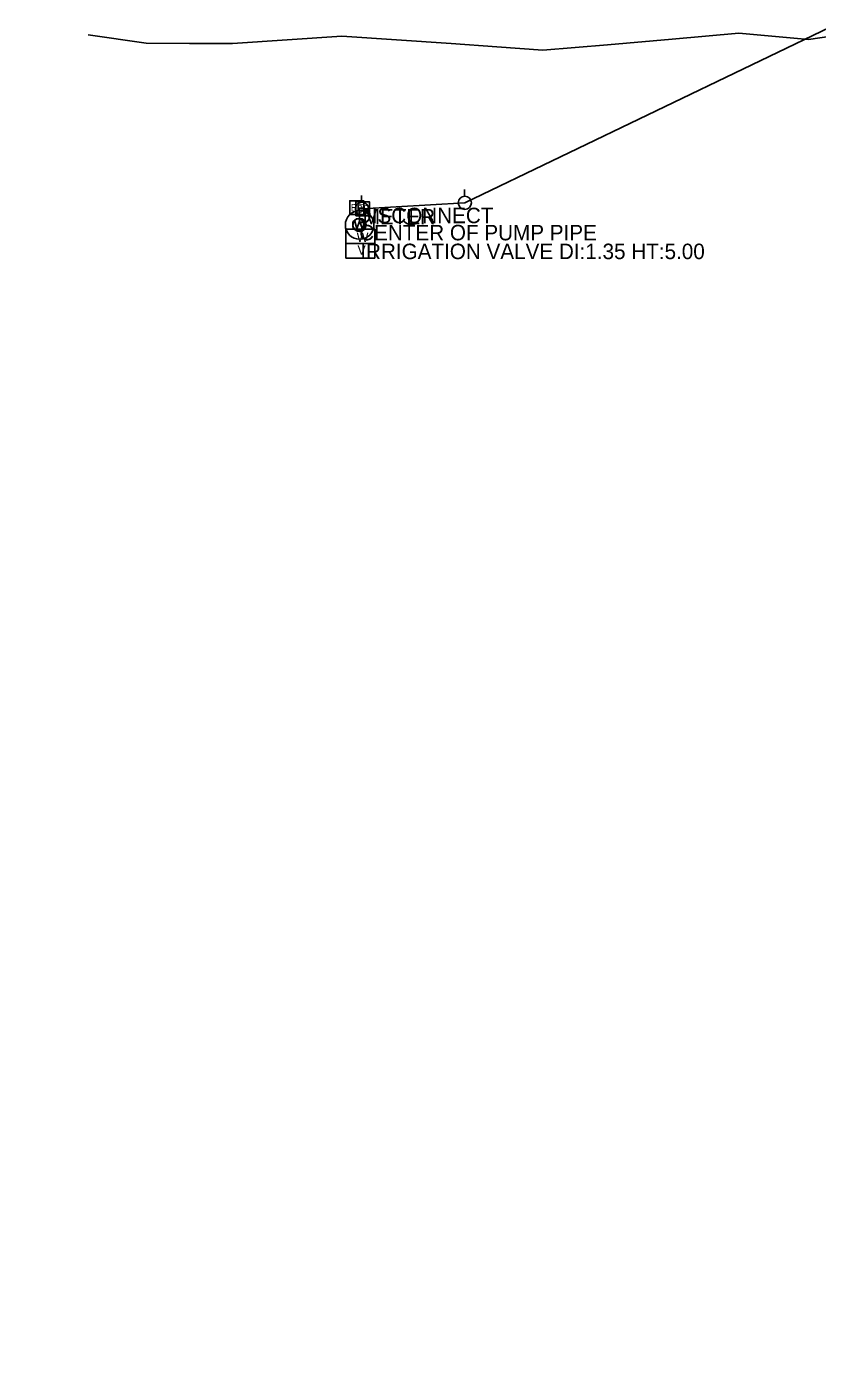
# Model space of a CAD drawing. Extents: x 1674300 to 1677920, y 225056 to 231852.
# Drawn here: x 1676889.4 to 1677145.4, y 228719.7 to 229147 of the extents above; entities that cross this region are included whole.
import ezdxf

# ---------------------------------------------------------------- set-up
doc = ezdxf.new("R2010")
doc.units = 0
for name, color, linetype in [('R_Horz Alg', 7, 'Continuous'), ('S_EDGE_CONCRETE', 7, 'Continuous'), ('S_ELECTRIC_UTILITIES', 7, 'Continuous'), ('S_ELECTRIC_UTILITIES_ANNOT', 7, 'Continuous'), ('S_EXIST_ROW', 7, 'Continuous'), ('S_STREAM', 7, 'Continuous'), ('S_UTILITY_POLE', 7, 'Continuous'), ('S_UTL_PT_SYM', 7, 'Continuous'), ('S_WATER_UTILITIES', 7, 'Continuous'), ('S_WATER_UTILITIES_ANNOT', 7, 'Continuous'), ('S_WATER_WELL_ANNOT', 7, 'Continuous')]:
    doc.layers.add(name, color=color, linetype=linetype)

msp = doc.modelspace()

# ---------------------------------------------------------------- linework, layer by layer
at = {"layer": 'R_Horz Alg'}
msp.add_arc((1675928.16, 228988.54), 1449, 296.0624, 0.80558, dxfattribs=at)
at = {"layer": 'S_EDGE_CONCRETE'}
msp.add_lwpolyline([(1676995.02, 229083.8), (1676994.98, 229082.04), (1676996.14, 229081.03), (1676997.58, 229080.98), (1676998.8, 229082.15), (1676998.7, 229083.76), (1676997.57, 229084.6), (1676996.22, 229084.77)], close=True, dxfattribs=at)
at = {"layer": 'S_ELECTRIC_UTILITIES'}
for p, q in [((1677278.13, 229208.63), (1677031.23, 229090)), ((1677031.23, 229090), (1676997.94, 229088.05))]:
    msp.add_line(p, q, dxfattribs=at)
for points in [[(1676994, 229086.15), (1676994, 229090.65), (1676998.5, 229090.65), (1676998.5, 229086.15)], [(1676995.91, 229085.75), (1676995.91, 229090.25), (1677000.41, 229090.25), (1677000.41, 229085.75)]]:
    msp.add_lwpolyline(points, close=True, dxfattribs=at)
at = {"layer": 'S_EXIST_ROW'}
msp.add_arc((1675926.71, 228989.39), 1410.53, 295.94359, 0.85682, dxfattribs=at)
at = {"layer": 'S_STREAM'}
msp.add_lwpolyline([(1677183.04, 229148.43), (1677170.36, 229146.92), (1677156.37, 229144.85), (1677142.38, 229142.77), (1677119.88, 229144.84), (1677098.3, 229142.91), (1677077.37, 229141.12), (1677056.44, 229139.33), (1677041.62, 229140.43), (1677026.8, 229141.54), (1677009.09, 229142.72), (1676991.39, 229143.9), (1676973.72, 229142.72), (1676956.05, 229141.55), (1676942.08, 229141.57), (1676928.12, 229141.58), (1676909.38, 229144.28)], dxfattribs=at)
at = {"layer": 'S_UTILITY_POLE'}
for p, q in [((1677031.11, 229092.14), (1677031.11, 229094.25)), ((1676997.81, 229090.19), (1676997.81, 229092.3)), ((1677013.87, 229087.68), (1677013.87, 229082.95))]:
    msp.add_line(p, q, dxfattribs=at)
for centre in [(1676997.94, 229088.05), (1677031.23, 229090)]:
    msp.add_circle(centre, 2.13, dxfattribs=at)
msp.add_arc((1677013.93, 229086.37), 3.41, 226.3972, 313.6028, dxfattribs=at)
at = {"layer": 'S_UTL_PT_SYM'}
for points in [[(1677031.23, 229090), (1677031.23, 229090.05), (1677031.23, 229090), (1677031.18, 229090), (1677031.23, 229090), (1677031.23, 229089.95), (1677031.23, 229090), (1677031.28, 229090)], [(1676997.94, 229088.05), (1676997.94, 229088.1), (1676997.94, 229088.05), (1676997.89, 229088.05), (1676997.94, 229088.05), (1676997.94, 229088), (1676997.94, 229088.05), (1676997.99, 229088.05)]]:
    msp.add_lwpolyline(points, dxfattribs=at)
at = {"layer": 'S_WATER_UTILITIES'}
for p, q in [((1676992.68, 229081.46), (1677002.1, 229081.46)), ((1676992.68, 229072.04), (1676992.68, 229081.46)), ((1676995.63, 229084.08), (1676996.29, 229081.6)), ((1676996.29, 229081.6), (1676997.1, 229084.08)), ((1676997.1, 229084.08), (1676998.15, 229081.6)), ((1676998.15, 229081.6), (1676998.73, 229084.12)), ((1677002.1, 229081.46), (1677002.1, 229072.04)), ((1676992.68, 229076.77), (1677002.1, 229076.77)), ((1677002.1, 229072.04), (1676992.68, 229072.04))]:
    msp.add_line(p, q, dxfattribs=at)
for centre, radius in [((1676997.19, 229082.82), 4.63), ((1676997.16, 229082.82), 2.13)]:
    msp.add_circle(centre, radius, dxfattribs=at)

# ---------------------------------------------------------------- texts
at = {"layer": 'S_ELECTRIC_UTILITIES'}
for p in [(1676994.31, 229087.2), (1676996.22, 229086.8)]:
    msp.add_text('BE', height=2.4, rotation=360, dxfattribs=at).set_placement(p)
at = {"layer": 'S_ELECTRIC_UTILITIES_ANNOT'}
for s, p in [('DISCONNECT', (1676996.27, 229083.4)), ('METER', (1676998.18, 229083))]:
    msp.add_text(s, height=5, dxfattribs=at).set_placement(p)
at = {"layer": 'S_WATER_UTILITIES'}
for s, p in [('W', (1676996.24, 229077.3)), ('V', (1676996.47, 229073.24))]:
    msp.add_text(s, height=3, rotation=360, dxfattribs=at).set_placement(p)
at = {"layer": 'S_WATER_UTILITIES_ANNOT'}
msp.add_text('IRRIGATION VALVE DI:1.35 HT:5.00', height=5, dxfattribs=at).set_placement((1676997.39, 229071.77))
at = {"layer": 'S_WATER_WELL_ANNOT'}
msp.add_text('CENTER OF PUMP PIPE', height=5, dxfattribs=at).set_placement((1676997.04, 229077.85))

doc.saveas('drawing.dxf')
